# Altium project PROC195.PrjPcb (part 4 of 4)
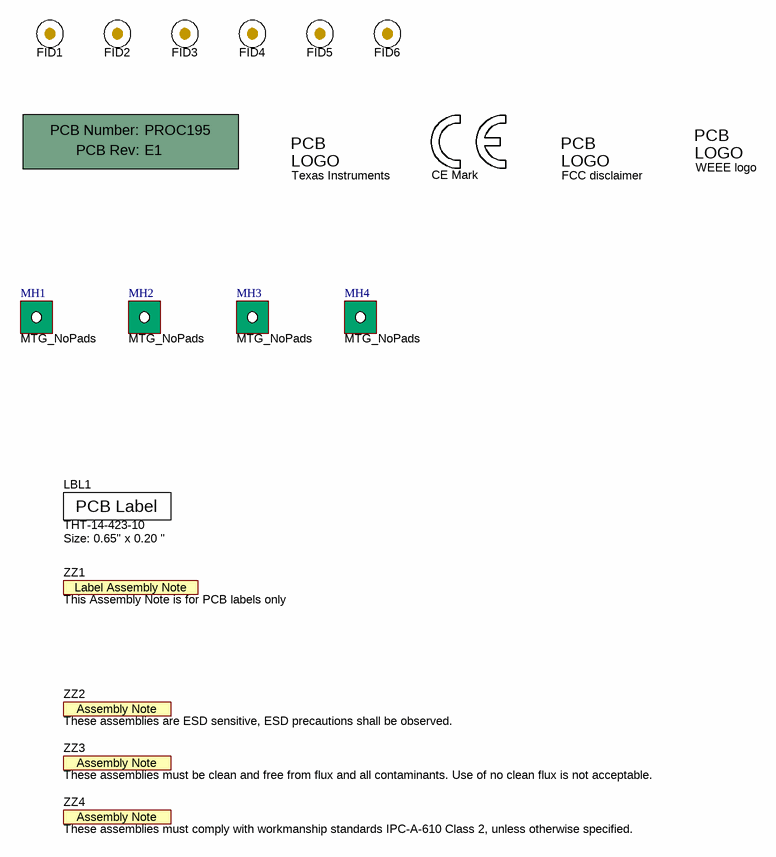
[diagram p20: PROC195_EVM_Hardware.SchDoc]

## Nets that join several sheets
1V8_LDO4: PROC195__FET_BOOST_REG (R265.1), PROC195_PMIC_BUCK (5 pins), PROC195_ADC (S1.1 S1.4)
3V3_LDO2: PROC195__FET_BOOST_REG (R57.1 R72.1), PROC195_PMIC_BUCK (C97.1 C98.1 TP7.1 U2.11), PROC195_CLK_LED_CURRENT_MON_TEMP_CONN (9 pins), PROC195_High_density_conn_1_2 (J1.28 R1.2)
5V0_LDO3: PROC195__FET_BOOST_REG (R160.1), PROC195_PMIC_BUCK (C99.1 C101.1 TP9.1 U2.15), PROC195_High_density_conn_1_2 (J1.34)
+1V2: PROC195_PMIC_BUCK (5 pins), PROC195_CLK_LED_CURRENT_MON_TEMP_CONN (R43.3)
GND: PROC195__FET_BOOST_REG (26 pins), PROC195_PMIC_BUCK (53 pins), PROC195_MCU_POWER_CAPS (147 pins), PROC195_SDFM, JTAG (9 pins), PROC195_OSPI_BOOTMODE (20 pins), PROC195_ADC (8 pins), PROC195_DAC (8 pins), PROC195_CLK_LED_CURRENT_MON_TEMP_CONN (23 pins), PROC195_RESET_CIRCUIT (21 pins), PROC195_High_density_conn_1_2 (20 pins), PROC195_High_density_conn3_4 (8 pins), PROC195_MIPI_Emulation_conn (10 pins)
VCC_1V2: PROC195_MCU_POWER_CAPS (47 pins), PROC195_CLK_LED_CURRENT_MON_TEMP_CONN (R43.4 TP16.1)
VDD_IO_3V3: PROC195_MCU_POWER_CAPS (20 pins), PROC195_CLK_LED_CURRENT_MON_TEMP_CONN (R44.4 TP17.1)
VDDA18_LDO_1V8: PROC195_MCU_POWER_CAPS (10 pins), PROC195_DAC (S2.1)
VDDA_3V3: PROC195_MCU_POWER_CAPS (8 pins), PROC195_ADC (C122.2 U11.4), PROC195_DAC (C152.1 U20.8)
VDDS18_LDO_1V8: PROC195_MCU_POWER_CAPS (11 pins), PROC195_CLK_LED_CURRENT_MON_TEMP_CONN (U7.5)
VMAIN_5V0: PROC195__FET_BOOST_REG (10 pins), PROC195_PMIC_BUCK (TP3.1), PROC195_MCU_POWER_CAPS (R12.2), PROC195_RESET_CIRCUIT (R249.1)
VMAIN_5V0_IN: PROC195__FET_BOOST_REG (5 pins), PROC195_High_density_conn_1_2 (J1.18 J1.20), PROC195_High_density_conn3_4 (J3.27)
VMAIN_12V0: PROC195__FET_BOOST_REG (C100.2 R190.2 U22.6), PROC195_PMIC_BUCK (18 pins)
VSYS_3V3_LDO1: PROC195__FET_BOOST_REG (R68.1 R279.2 R280.2), PROC195_PMIC_BUCK (10 pins), PROC195_EPWM (R104.2 R105.2), PROC195_SDFM, JTAG (12 pins), PROC195_OSPI_BOOTMODE (34 pins), PROC195_ADC (7 pins), PROC195_DAC (8 pins), PROC195_CLK_LED_CURRENT_MON_TEMP_CONN (13 pins), PROC195_RESET_CIRCUIT (19 pins), PROC195_MIPI_Emulation_conn (5 pins)
15W_PD: PROC195__FET_BOOST_REG (R42.2 R82.1 U14.3), PROC195_High_density_conn_1_2 (J1.26)
+1V2_PG: PROC195_PMIC_BUCK (R37.1 U3.1), PROC195_RESET_CIRCUIT (U21.1)
ADC0_AIN0/DAC_OUT_MUX_SEL: PROC195_SDFM, JTAG (U12.3), PROC195_DAC (U20.1 U20.5)
ADC_VREFHI_G2_G3: PROC195_EPWM (R239.1), PROC195_ADC (5 pins)
AM26x_ADC0_AIN0: PROC195_ADC (U1.V15), PROC195_DAC (U20.2)
AM26x_ADC0_AIN0/DAC_OUT: PROC195_DAC (U20.10), PROC195_High_density_conn_1_2 (J1.119)
AM26x_ADC0_AIN1: PROC195_ADC (U1.U15), PROC195_High_density_conn_1_2 (J1.117)
AM26x_ADC0_AIN2_P: PROC195_ADC (U1.T14), PROC195_High_density_conn_1_2 (J1.120)
AM26x_ADC0_AIN3_N: PROC195_ADC (U1.U14), PROC195_High_density_conn_1_2 (J1.118)
AM26x_ADC0_AIN4_P: PROC195_ADC (U1.U13), PROC195_High_density_conn_1_2 (J1.115)
AM26x_ADC0_AIN5_N: PROC195_ADC (U1.R14), PROC195_High_density_conn_1_2 (J1.113)
AM26x_ADC1_AIN0_P: PROC195_ADC (U1.T11), PROC195_High_density_conn_1_2 (J1.116)
AM26x_ADC1_AIN1_N: PROC195_ADC (U1.U11), PROC195_High_density_conn_1_2 (J1.114)
AM26x_ADC1_AIN2_P: PROC195_ADC (U1.T12), PROC195_High_density_conn_1_2 (J1.111)
AM26x_ADC1_AIN3_N: PROC195_ADC (U1.V12), PROC195_High_density_conn_1_2 (J1.109)
AM26x_ADC1_AIN4: PROC195_ADC (U1.U12), PROC195_High_density_conn_1_2 (J1.112)
AM26x_ADC1_AIN5: PROC195_ADC (U1.R12), PROC195_High_density_conn_1_2 (J1.110)
AM26x_ADC2_AIN0_P: PROC195_ADC (U1.R10), PROC195_High_density_conn_1_2 (J1.107)
AM26x_ADC2_AIN1_N: PROC195_ADC (U1.T10), PROC195_High_density_conn_1_2 (J1.105)
AM26x_ADC2_AIN2_P: PROC195_ADC (U1.U10), PROC195_High_density_conn_1_2 (J1.108)
AM26x_ADC2_AIN3_N: PROC195_ADC (U1.T9), PROC195_High_density_conn_1_2 (J1.106)
AM26x_ADC2_AIN4: PROC195_ADC (U1.V9), PROC195_High_density_conn_1_2 (J1.103)
AM26x_ADC2_AIN5: PROC195_ADC (U1.T8), PROC195_High_density_conn_1_2 (J1.101)
AM26x_ADC3_AIN0_P: PROC195_ADC (R240.1), PROC195_High_density_conn_1_2 (J1.104)
AM26x_ADC3_AIN1_N: PROC195_ADC (R241.1), PROC195_High_density_conn_1_2 (J1.102)
AM26x_ADC3_AIN2_P: PROC195_ADC (R242.1), PROC195_High_density_conn_1_2 (J1.99)
AM26x_ADC3_AIN3_N: PROC195_ADC (R243.1), PROC195_High_density_conn_1_2 (J1.97)
AM26x_ADC3_AIN4: PROC195_ADC (R244.1), PROC195_High_density_conn_1_2 (J1.100)
AM26x_ADC3_AIN5: PROC195_ADC (R272.1), PROC195_High_density_conn_1_2 (J1.98)
AM26x_ADC4_AIN0_P: PROC195_ADC (R273.1), PROC195_High_density_conn_1_2 (J1.95)
AM26x_ADC4_AIN1_N: PROC195_ADC (R274.1), PROC195_High_density_conn_1_2 (J1.93)
AM26x_ADC4_AIN2_P: PROC195_ADC (R275.1), PROC195_High_density_conn_1_2 (J1.96)
AM26x_ADC4_AIN3_N: PROC195_ADC (R276.1), PROC195_High_density_conn_1_2 (J1.94)
AM26x_ADC4_AIN4: PROC195_ADC (R277.1), PROC195_High_density_conn_1_2 (J1.91)
AM26x_ADC4_AIN5: PROC195_ADC (R278.1), PROC195_High_density_conn_1_2 (J1.89)
AM26x_ADC_CAL0: PROC195_ADC (U1.U16), PROC195_High_density_conn_1_2 (J1.92)
AM26x_ADC_CAL1: PROC195_ADC (R77.2), PROC195_High_density_conn_1_2 (J1.90)
AM26x_ADC_CAL2: PROC195_DAC (R283.2), PROC195_High_density_conn_1_2 (J2.112)
AM26x_ADC_CAL3: PROC195_DAC (R297.2), PROC195_High_density_conn_1_2 (J2.110)
AM26x_ADC_R0_AIN0_P: PROC195_DAC (R289.2), PROC195_High_density_conn_1_2 (J2.120)
AM26x_ADC_R0_AIN1_N: PROC195_EPWM (R261.1), PROC195_High_density_conn_1_2 (J2.118)
AM26x_ADC_R0_AIN2_P: PROC195_DAC (R287.2), PROC195_High_density_conn_1_2 (J2.119)
AM26x_ADC_R0_AIN3_N: PROC195_DAC (R285.2), PROC195_High_density_conn_1_2 (J2.117)
AM26x_ADC_R1_AIN0_P: PROC195_EPWM (R263.1), PROC195_High_density_conn_1_2 (J2.116)
AM26x_ADC_R1_AIN1_N: PROC195_DAC (R291.2), PROC195_High_density_conn_1_2 (J2.114)
AM26x_ADC_R1_AIN2_P: PROC195_DAC (R295.2), PROC195_High_density_conn_1_2 (J2.115)
AM26x_ADC_R1_AIN3_N: PROC195_DAC (R293.2), PROC195_High_density_conn_1_2 (J2.113)
AM26x_EPWM0_A: PROC195_EPWM (R106.1), PROC195_High_density_conn_1_2 (J1.15)
AM26x_EPWM0_B: PROC195_EPWM (R107.1), PROC195_High_density_conn_1_2 (J1.13)
AM26x_EPWM1_A: PROC195_EPWM (R109.1), PROC195_High_density_conn_1_2 (J1.11)
AM26x_EPWM1_B: PROC195_EPWM (R111.1), PROC195_High_density_conn_1_2 (J1.9)
AM26x_EPWM2_A: PROC195_EPWM (R112.1), PROC195_High_density_conn_1_2 (J1.7)
AM26x_EPWM2_B: PROC195_EPWM (R113.1), PROC195_High_density_conn_1_2 (J1.5)
AM26x_EPWM3_A: PROC195_EPWM (R114.1), PROC195_High_density_conn_1_2 (J1.3)
AM26x_EPWM3_B: PROC195_EPWM (R115.1), PROC195_High_density_conn_1_2 (J1.1)
AM26x_EPWM4_A: PROC195_EPWM (R116.1), PROC195_High_density_conn_1_2 (J1.16)
AM26x_EPWM4_B: PROC195_EPWM (R117.1), PROC195_High_density_conn_1_2 (J1.14)
AM26x_EPWM5_A: PROC195_EPWM (R118.1), PROC195_High_density_conn_1_2 (J1.12)
AM26x_EPWM5_B: PROC195_EPWM (R120.1), PROC195_High_density_conn_1_2 (J1.10)
AM26x_EPWM6_A: PROC195_EPWM (R123.1), PROC195_High_density_conn_1_2 (J1.8)
AM26x_EPWM6_B: PROC195_EPWM (R125.1), PROC195_High_density_conn_1_2 (J1.6)
AM26x_EPWM7_A: PROC195_EPWM (R127.1), PROC195_High_density_conn_1_2 (J1.4)
AM26x_EPWM7_B: PROC195_EPWM (R128.1), PROC195_High_density_conn_1_2 (J1.2)
AM26x_EPWM8_A: PROC195_EPWM (R130.1), PROC195_High_density_conn_1_2 (J2.60)
AM26x_EPWM8_B: PROC195_EPWM (R131.1), PROC195_High_density_conn_1_2 (J2.58)
AM26x_EPWM9_A: PROC195_EPWM (R133.1), PROC195_High_density_conn_1_2 (J2.56)
AM26x_EPWM9_B: PROC195_EPWM (R134.1), PROC195_High_density_conn_1_2 (J2.54)
AM26x_EQEP0_A: PROC195_EPWM (R83.1), PROC195_High_density_conn_1_2 (J1.71)
AM26x_EQEP0_B: PROC195_EPWM (R85.1), PROC195_High_density_conn_1_2 (J1.69)
AM26x_EQEP0_INDEX: PROC195_EPWM (U1.D11), PROC195_High_density_conn_1_2 (J1.65)
AM26x_EQEP0_STROBE: PROC195_EPWM (U1.C12), PROC195_High_density_conn_1_2 (J1.67)
AM26x_FSIRX0_CLK: PROC195_RESET_CIRCUIT (U24.3), PROC195_High_density_conn_1_2 (J1.55)
AM26x_FSIRX0_DATA0: PROC195_RESET_CIRCUIT (U24.6), PROC195_High_density_conn_1_2 (J1.59)
AM26x_FSIRX0_DATA1: PROC195_RESET_CIRCUIT (U24.10), PROC195_High_density_conn_1_2 (J1.57)
AM26x_FSITX0_CLK: PROC195_DAC (U13.3), PROC195_High_density_conn_1_2 (J1.49)
AM26x_FSITX0_DATA0: PROC195_DAC (U13.6), PROC195_High_density_conn_1_2 (J1.53)
AM26x_FSITX0_DATA1: PROC195_DAC (U13.10), PROC195_High_density_conn_1_2 (J1.51)
AM26x_GPIO15: PROC195_RESET_CIRCUIT (U24.13), PROC195_High_density_conn3_4 (J3.57)
AM26x_I2C1_SCL: PROC195_SDFM, JTAG (R268.1 U25.2), PROC195_High_density_conn3_4 (J3.70)
AM26x_I2C1_SDA: PROC195_SDFM, JTAG (R266.1 U1.A3), PROC195_High_density_conn3_4 (J3.72)
AM26x_I2C2_SCL: PROC195_SDFM, JTAG (R158.1 U1.C6), PROC195_High_density_conn_1_2 (J1.61)
AM26x_I2C2_SDA: PROC195_SDFM, JTAG (R157.1 U1.A5), PROC195_High_density_conn_1_2 (J1.63)
AM26x_LIN1_RXD: PROC195_OSPI_BOOTMODE (U1.A9), PROC195_High_density_conn_1_2 (J1.37)
AM26x_LIN1_TXD: PROC195_OSPI_BOOTMODE (R211.1), PROC195_High_density_conn_1_2 (J1.35)
AM26x_MCAN0_RX: PROC195_SDFM, JTAG (U1.B6), PROC195_High_density_conn_1_2 (J1.38)
AM26x_MCAN0_TX: PROC195_SDFM, JTAG (R129.1), PROC195_High_density_conn_1_2 (J1.36)
AM26x_MCAN1_RX: PROC195_SDFM, JTAG (U25.3), PROC195_High_density_conn3_4 (J3.56)
AM26x_MCAN1_TX: PROC195_SDFM, JTAG (R132.1), PROC195_High_density_conn3_4 (J3.54)
AM26x_SDFM0_CLK0: PROC195_SDFM, JTAG (R76.1), PROC195_High_density_conn_1_2 (J1.54)
AM26x_SDFM0_D0: PROC195_SDFM, JTAG (U1.D14), PROC195_High_density_conn_1_2 (J1.60)
AM26x_SDFM0_D1: PROC195_SDFM, JTAG (U1.D13), PROC195_High_density_conn_1_2 (J1.58)
AM26x_SDFM0_D2: PROC195_SDFM, JTAG (U1.C13), PROC195_High_density_conn_1_2 (J1.56)
AM26x_SDFM0_D3: PROC195_SDFM, JTAG (U1.C14), PROC195_High_density_conn_1_2 (J1.50)
AM26x_SPI0_CLK: PROC195_DAC (U13.2), PROC195_High_density_conn_1_2 (J2.34)
AM26x_SPI0_CS0: PROC195_DAC (U13.14), PROC195_High_density_conn_1_2 (J2.36)
AM26x_SPI0_D0: PROC195_DAC (U13.5), PROC195_High_density_conn_1_2 (J2.32)
AM26x_SPI0_D1: PROC195_DAC (U13.11), PROC195_High_density_conn_1_2 (J2.30)
AM26x_SPI3_CLK: PROC195_ADC (U18.2), PROC195_High_density_conn_1_2 (J1.41)
AM26x_SPI3_CS0: PROC195_ADC (U18.14), PROC195_High_density_conn_1_2 (J1.39)
AM26x_SPI3_D0: PROC195_ADC (U18.5), PROC195_High_density_conn_1_2 (J1.45)
AM26x_SPI3_D1: PROC195_ADC (U18.11), PROC195_High_density_conn_1_2 (J1.43)
AM26x_TCK: PROC195_SDFM, JTAG (U1.B3), PROC195_MIPI_Emulation_conn (R61.1 R314.2)
AM26x_TDI: PROC195_SDFM, JTAG (U1.C5), PROC195_MIPI_Emulation_conn (R63.1 R316.2)
AM26x_TDO: PROC195_SDFM, JTAG (R162.1), PROC195_MIPI_Emulation_conn (R62.1 R315.2)
AM26x_TMS: PROC195_SDFM, JTAG (U1.D5), PROC195_MIPI_Emulation_conn (R60.1 R313.2)
AM26x_UART0_RXD: PROC195_OSPI_BOOTMODE (U1.A7), PROC195_High_density_conn_1_2 (J1.33), PROC195_MIPI_Emulation_conn (J7.9)
AM26x_UART0_TXD: PROC195_OSPI_BOOTMODE (R208.1), PROC195_High_density_conn_1_2 (J1.31), PROC195_MIPI_Emulation_conn (J7.10)
AM26x_UART2_RXD: PROC195_OSPI_BOOTMODE (R212.1), PROC195_High_density_conn_1_2 (J2.26)
AM26x_UART2_TXD: PROC195_OSPI_BOOTMODE (U1.A8), PROC195_High_density_conn_1_2 (J2.28)
AM26x_USB0_DM: PROC195_SDFM, JTAG (R165.1), PROC195_High_density_conn_1_2 (J2.40)
AM26x_USB0_DP: PROC195_SDFM, JTAG (R168.1), PROC195_High_density_conn_1_2 (J2.38)
AM26x_VREFHI1: PROC195_ADC (S1.3), PROC195_High_density_conn_1_2 (J1.85)
AM26x_VREFHI2: PROC195_ADC (S1.6), PROC195_High_density_conn_1_2 (J1.83)
AM26x_VREFLO: PROC195_ADC (10 pins), PROC195_High_density_conn_1_2 (J1.87)
DAC_SPI3_CLK: PROC195_ADC (U18.3), PROC195_MIPI_Emulation_conn (J7.13)
DAC_SPI3_CS0: PROC195_ADC (U18.13), PROC195_MIPI_Emulation_conn (J7.16)
DAC_SPI3_D0: PROC195_ADC (U18.6), PROC195_MIPI_Emulation_conn (J7.14)
DAC_SPI3_D1: PROC195_ADC (U18.10), PROC195_MIPI_Emulation_conn (J7.15)
DAC_TCK: PROC195_High_density_conn_1_2 (J1.22), PROC195_MIPI_Emulation_conn (J7.4 R314.1)
DAC_TDI: PROC195_High_density_conn_1_2 (J1.19), PROC195_MIPI_Emulation_conn (J7.5 R316.1)
DAC_TDO: PROC195_High_density_conn_1_2 (J1.21), PROC195_MIPI_Emulation_conn (J7.6 R315.1)
DAC_TMS: PROC195_High_density_conn_1_2 (J1.24), PROC195_MIPI_Emulation_conn (J7.3 R313.1)
EXT_VMON2: PROC195_PMIC_BUCK (U2.10), PROC195_High_density_conn3_4 (J3.59)
EXT_VREF2: PROC195_ADC (S1.5 U11.5), PROC195_DAC (U11.14)
IOEXP_OUT_P6: PROC195_SDFM, JTAG (U12.9), PROC195_High_density_conn_1_2 (J2.5)
IOEXP_OUT_P7: PROC195_SDFM, JTAG (U12.10), PROC195_High_density_conn_1_2 (J2.9)
JTAG_RESETn: PROC195_RESET_CIRCUIT (U4.3), PROC195_MIPI_Emulation_conn (R40.1 R64.1)
MCU_GPIO1: PROC195_OSPI_BOOTMODE (R140.1), PROC195_High_density_conn_1_2 (J1.52)
MCU_GPIO41: PROC195_DAC (R233.1 R236.1), PROC195_High_density_conn_1_2 (J2.19)
MCU_GPIO42: PROC195_DAC (R234.1 R235.1), PROC195_High_density_conn_1_2 (J2.17)
MCU_GPIO63: PROC195_EPWM (R135.1), PROC195_High_density_conn_1_2 (J2.52)
MCU_GPIO64: PROC195_EPWM (R136.1), PROC195_High_density_conn_1_2 (J2.50)
MCU_GPIO67: PROC195_EPWM (R143.1), PROC195_High_density_conn_1_2 (J2.59)
MCU_GPIO68: PROC195_EPWM (R144.1), PROC195_High_density_conn_1_2 (J2.57)
MCU_GPIO69: PROC195_EPWM (R146.1), PROC195_High_density_conn_1_2 (J2.55)
MCU_GPIO70: PROC195_EPWM (R147.1), PROC195_High_density_conn_1_2 (J2.53)
MCU_GPIO73: PROC195_EPWM (R282.1), PROC195_High_density_conn_1_2 (J1.75)
MCU_GPIO74: PROC195_EPWM (R262.1), PROC195_High_density_conn_1_2 (J2.25)
MCU_GPIO82: PROC195_SDFM, JTAG (U1.A2 U25.1), PROC195_High_density_conn_1_2 (J1.48)
MCU_GPIO85: PROC195_EPWM (R104.1 R110.1), PROC195_High_density_conn3_4 (J3.99)
MCU_GPIO86: PROC195_EPWM (R105.1 R108.1), PROC195_High_density_conn3_4 (J3.97)
MCU_GPIO119: PROC195_EPWM (R173.1), PROC195_High_density_conn3_4 (J3.66)
MCU_GPIO120: PROC195_EPWM (R172.1), PROC195_High_density_conn3_4 (J3.68)
MCU_GPIO121: PROC195_RESET_CIRCUIT (R312.2), PROC195_High_density_conn_1_2 (J1.70)
MCU_GPIO124: PROC195_SDFM, JTAG (R214.1), PROC195_High_density_conn_1_2 (J1.72)
MCU_GPIO126: PROC195_SDFM, JTAG (U1.B15), PROC195_High_density_conn_1_2 (J1.73)
MCU_GPIO136: PROC195_OSPI_BOOTMODE (R217.1), PROC195_High_density_conn_1_2 (J2.23)
MCU_GPIO137: PROC195_OSPI_BOOTMODE (U1.A12), PROC195_High_density_conn_1_2 (J2.21)
MCU_GPIO138: PROC195_RESET_CIRCUIT (R138.2), PROC195_High_density_conn_1_2 (J1.74)
MCU_I2C0_SCL: PROC195_SDFM, JTAG (U12.12), PROC195_OSPI_BOOTMODE (R38.1 R202.1), PROC195_CLK_LED_CURRENT_MON_TEMP_CONN (5 pins), PROC195_High_density_conn_1_2 (J1.23), PROC195_MIPI_Emulation_conn (J7.12)
MCU_I2C0_SDA: PROC195_SDFM, JTAG (U12.13), PROC195_OSPI_BOOTMODE (R39.1 R203.1), PROC195_CLK_LED_CURRENT_MON_TEMP_CONN (5 pins), PROC195_High_density_conn_1_2 (J1.25), PROC195_MIPI_Emulation_conn (J7.11)
MCU_INTn: PROC195_SDFM, JTAG (U1.A15), PROC195_RESET_CIRCUIT (R41.2 U23.5)
MCU_PORz: PROC195_SDFM, JTAG (U12.1), PROC195_OSPI_BOOTMODE (R231.1 U16.2), PROC195_RESET_CIRCUIT (TP18.1 U1.R2 U4.4), PROC195_High_density_conn_1_2 (J1.29)
MCU_RESETn: PROC195_OSPI_BOOTMODE (R232.1), PROC195_RESET_CIRCUIT (R253.2 U1.C3 U23.2)
MCU_SPI0_CLK: PROC195_OSPI_BOOTMODE (R225.1 U1.A11), PROC195_DAC (R298.2 U13.4)
MCU_SPI0_CS0: PROC195_OSPI_BOOTMODE (U1.C11), PROC195_DAC (R301.2 U13.12)
MCU_SPI0_D0: PROC195_OSPI_BOOTMODE (R226.1 U1.C10), PROC195_DAC (R299.2 U13.7)
MCU_SPI0_D1: PROC195_OSPI_BOOTMODE (U1.B11), PROC195_DAC (R300.2 U13.9)
MCU_SPI1_CLK: PROC195_OSPI_BOOTMODE (U1.A10), PROC195_RESET_CIRCUIT (R254.2 U24.4)
MCU_SPI1_CS0: PROC195_OSPI_BOOTMODE (U1.C9), PROC195_RESET_CIRCUIT (R257.2 U24.12)
MCU_SPI1_D0: PROC195_OSPI_BOOTMODE (U1.B10), PROC195_RESET_CIRCUIT (R255.2 U24.7)
MCU_SPI1_D1: PROC195_OSPI_BOOTMODE (U1.D9), PROC195_RESET_CIRCUIT (R256.2 U24.9)
MCU_SPI3_CLK: PROC195_OSPI_BOOTMODE (R204.1), PROC195_ADC (R304.2 U18.4)
MCU_SPI3_CS0: PROC195_OSPI_BOOTMODE (U1.D7), PROC195_ADC (R308.2 U18.12)
MCU_SPI3_D0: PROC195_OSPI_BOOTMODE (R207.1), PROC195_ADC (R306.2 U18.7)
MCU_SPI3_D1: PROC195_OSPI_BOOTMODE (U1.B7), PROC195_ADC (R307.2 U18.9)
MII_RST#: PROC195_SDFM, JTAG (U12.4), PROC195_High_density_conn3_4 (J3.101)
MII_RX_ER: PROC195_EPWM (R4.1), PROC195_High_density_conn_1_2 (J2.15)
OSPI0_ECS: PROC195_EPWM (U1.H1), PROC195_OSPI_BOOTMODE (R185.1 U15.A5)
OSPI0_RESET_OUTn: PROC195_EPWM (U1.J1), PROC195_OSPI_BOOTMODE (R205.1 U16.1)
PHY0_25MHZ_CLK: PROC195_CLK_LED_CURRENT_MON_TEMP_CONN (R210.2), PROC195_High_density_conn3_4 (J3.117)
PHY1_25MHZ_CLK: PROC195_CLK_LED_CURRENT_MON_TEMP_CONN (R213.2), PROC195_High_density_conn3_4 (J3.119)
PMIC_COMP1_IN+: PROC195_PMIC_BUCK (U2.21), PROC195_High_density_conn3_4 (J3.37)
PMIC_COMP1_IN-: PROC195_PMIC_BUCK (U2.24), PROC195_High_density_conn3_4 (J3.35)
PMIC_COMP2_IN+: PROC195_PMIC_BUCK (U2.28), PROC195_High_density_conn3_4 (J3.33)
PMIC_COMP2_IN-: PROC195_PMIC_BUCK (U2.25), PROC195_High_density_conn3_4 (J3.31)
PMIC_DIAG_OUT: PROC195_PMIC_BUCK (U2.32), PROC195_RESET_CIRCUIT (R84.2)
PMIC_INTn: PROC195_PMIC_BUCK (U2.22), PROC195_RESET_CIRCUIT (R311.2)
PMIC_nRST: PROC195_PMIC_BUCK (U2.13), PROC195_RESET_CIRCUIT (R247.1)
PMIC_SAFE_OUT1: PROC195_PMIC_BUCK (R25.2), PROC195_High_density_conn_1_2 (R1.1 R2.2 R74.2)
PMIC_SAFE_OUT2: PROC195__FET_BOOST_REG (Q4.1 R281.2), PROC195_PMIC_BUCK (U2.27), PROC195_High_density_conn3_4 (J3.29)
PMIC_SPI1/FSIRX0_MUX_SEL: PROC195_SDFM, JTAG (U12.2), PROC195_RESET_CIRCUIT (R258.1 U24.1)
PMIC_SPI1_CLK: PROC195_PMIC_BUCK (R19.2 TP11.1 U2.33), PROC195_RESET_CIRCUIT (U24.2)
PMIC_SPI1_CS0: PROC195_PMIC_BUCK (R22.2 TP14.1 U2.36), PROC195_RESET_CIRCUIT (U24.14)
PMIC_SPI1_D0: PROC195_PMIC_BUCK (R20.2 TP12.1 U2.35), PROC195_RESET_CIRCUIT (U24.5)
PMIC_SPI1_D1: PROC195_PMIC_BUCK (R21.2 R24.1), PROC195_RESET_CIRCUIT (U24.11)
PMIC_WAKE2: PROC195_PMIC_BUCK (U2.43), PROC195_High_density_conn_1_2 (J1.30)
PR0_PRU0_GPIO0: PROC195_EPWM (U1.K17), PROC195_High_density_conn3_4 (J3.102)
PR0_PRU0_GPIO1: PROC195_EPWM (U1.K18), PROC195_High_density_conn3_4 (J3.104)
PR0_PRU0_GPIO2: PROC195_EPWM (U1.J18), PROC195_High_density_conn3_4 (J3.106)
PR0_PRU0_GPIO3: PROC195_EPWM (U1.J17), PROC195_High_density_conn3_4 (J3.108)
PR0_PRU0_GPIO4: PROC195_EPWM (U1.K16), PROC195_High_density_conn3_4 (J3.113)
PR0_PRU0_GPIO5: PROC195_EPWM (U1.G17), PROC195_High_density_conn3_4 (J3.111)
PR0_PRU0_GPIO6: PROC195_EPWM (U1.K15), PROC195_High_density_conn3_4 (J3.100)
PR0_PRU0_GPIO8: PROC195_EPWM (U1.G15), PROC195_High_density_conn3_4 (J3.87)
PR0_PRU0_GPIO9: PROC195_EPWM (U1.F17), PROC195_High_density_conn3_4 (J3.105)
PR0_PRU0_GPIO10: PROC195_EPWM (U1.G18), PROC195_High_density_conn3_4 (J3.109)
PR0_PRU0_GPIO11: PROC195_EPWM (R119.1), PROC195_High_density_conn3_4 (J3.114)
PR0_PRU0_GPIO12: PROC195_EPWM (R121.1), PROC195_High_density_conn3_4 (J3.116)
PR0_PRU0_GPIO13: PROC195_EPWM (R122.1), PROC195_High_density_conn3_4 (J3.118)
PR0_PRU0_GPIO14: PROC195_EPWM (R124.1), PROC195_High_density_conn3_4 (J3.120)
PR0_PRU0_GPIO15: PROC195_EPWM (U1.L16), PROC195_High_density_conn3_4 (J3.115)
PR0_PRU0_GPIO16: PROC195_EPWM (R126.1), PROC195_High_density_conn3_4 (J3.112)
PR0_PRU1_GPIO0: PROC195_EPWM (R149.1), PROC195_High_density_conn3_4 (J3.78)
PR0_PRU1_GPIO1: PROC195_EPWM (R150.1), PROC195_High_density_conn3_4 (J3.80)
PR0_PRU1_GPIO2: PROC195_EPWM (R151.1), PROC195_High_density_conn3_4 (J3.82)
PR0_PRU1_GPIO3: PROC195_EPWM (R152.1), PROC195_High_density_conn3_4 (J3.84)
PR0_PRU1_GPIO4: PROC195_EPWM (R153.1), PROC195_High_density_conn3_4 (J3.93)
PR0_PRU1_GPIO5: PROC195_EPWM (R154.1), PROC195_High_density_conn3_4 (J3.95)
PR0_PRU1_GPIO6: PROC195_EPWM (R155.1), PROC195_High_density_conn3_4 (J3.76)
PR0_PRU1_GPIO8: PROC195_EPWM (R156.1), PROC195_High_density_conn3_4 (J3.89)
PR0_PRU1_GPIO9: PROC195_EPWM (R159.1), PROC195_High_density_conn3_4 (J3.85)
PR0_PRU1_GPIO10: PROC195_EPWM (R161.1), PROC195_High_density_conn3_4 (J3.83)
PR0_PRU1_GPIO11: PROC195_EPWM (R163.1), PROC195_High_density_conn3_4 (J3.90)
PR0_PRU1_GPIO12: PROC195_EPWM (R164.1), PROC195_High_density_conn3_4 (J3.92)
PR0_PRU1_GPIO13: PROC195_EPWM (R167.1), PROC195_High_density_conn3_4 (J3.94 R8.1)
PR0_PRU1_GPIO14: PROC195_EPWM (R169.1), PROC195_High_density_conn3_4 (J3.96 R5.1)
PR0_PRU1_GPIO15: PROC195_EPWM (R170.1), PROC195_High_density_conn3_4 (J3.91)
PR0_PRU1_GPIO16: PROC195_EPWM (R171.1), PROC195_High_density_conn3_4 (J3.88)
R_MCU_GPIO119: PROC195_EPWM (R173.2 U1.D15), PROC195_MIPI_Emulation_conn (R93.1)
R_MCU_GPIO120: PROC195_EPWM (R172.2 U1.C15), PROC195_MIPI_Emulation_conn (R96.1)
R_PR0_PRU1_GPIO0: PROC195_EPWM (R149.2 U1.F18), PROC195_MIPI_Emulation_conn (R86.2)
R_PR0_PRU1_GPIO1: PROC195_EPWM (R150.2 U1.G16), PROC195_MIPI_Emulation_conn (R87.2)
R_PR0_PRU1_GPIO2: PROC195_EPWM (R151.2 U1.E17), PROC195_MIPI_Emulation_conn (R88.2)
R_PR0_PRU1_GPIO3: PROC195_EPWM (R152.2 U1.E18), PROC195_MIPI_Emulation_conn (R89.2)
R_PR0_PRU1_GPIO4: PROC195_EPWM (R153.2 U1.F16), PROC195_MIPI_Emulation_conn (R103.1)
R_PR0_PRU1_GPIO5: PROC195_EPWM (R154.2 U1.F15), PROC195_MIPI_Emulation_conn (R98.1)
R_PR0_PRU1_GPIO6: PROC195_EPWM (R155.2 U1.E16), PROC195_MIPI_Emulation_conn (R102.1)
R_PR0_PRU1_GPIO8: PROC195_EPWM (R156.2 U1.D18), PROC195_MIPI_Emulation_conn (R101.1)
R_PR0_PRU1_GPIO9: PROC195_EPWM (R159.2 U1.C18), PROC195_MIPI_Emulation_conn (R99.1)
R_PR0_PRU1_GPIO10: PROC195_EPWM (R161.2 U1.D17), PROC195_MIPI_Emulation_conn (R100.1)
R_PR0_PRU1_GPIO11: PROC195_EPWM (R137.1 R163.2), PROC195_MIPI_Emulation_conn (R92.2)
R_PR0_PRU1_GPIO12: PROC195_EPWM (R139.1 R164.2), PROC195_MIPI_Emulation_conn (R94.2)
R_PR0_PRU1_GPIO13: PROC195_EPWM (R141.1 R167.2), PROC195_MIPI_Emulation_conn (R95.2)
R_PR0_PRU1_GPIO14: PROC195_EPWM (R142.1 R169.2), PROC195_MIPI_Emulation_conn (R97.2)
R_PR0_PRU1_GPIO15: PROC195_EPWM (R170.2 U1.A17), PROC195_MIPI_Emulation_conn (R91.2)
R_PR0_PRU1_GPIO16: PROC195_EPWM (R145.1 R171.2), PROC195_MIPI_Emulation_conn (R90.2)
RES0_PWMOUT0: PROC195_High_density_conn_1_2 (J2.48), PROC195_High_density_conn3_4 (R8.2)
RES0_PWMOUT1: PROC195_High_density_conn_1_2 (J2.46), PROC195_High_density_conn3_4 (R5.2)
RGMII1_ETH1_CLK: PROC195_CLK_LED_CURRENT_MON_TEMP_CONN (R3.2), PROC195_High_density_conn_1_2 (J2.1)
RGMII1_INTn: PROC195_EPWM (R79.1), PROC195_High_density_conn_1_2 (J2.7)
RGMII1_RD0: PROC195_DAC (R264.2), PROC195_High_density_conn_1_2 (J2.20)
RGMII1_RD1: PROC195_DAC (R284.2), PROC195_High_density_conn_1_2 (J2.18)
RGMII1_RD2: PROC195_DAC (R286.2), PROC195_High_density_conn_1_2 (J2.16)
RGMII1_RD3: PROC195_DAC (R288.2), PROC195_High_density_conn_1_2 (J2.14)
RGMII1_RST: PROC195_SDFM, JTAG (U12.5), PROC195_High_density_conn_1_2 (J2.11)
RGMII1_RX_CTL: PROC195_DAC (R290.2), PROC195_High_density_conn_1_2 (J2.13)
RGMII1_RXC: PROC195_DAC (U1.R17), PROC195_High_density_conn_1_2 (J2.22)
RGMII1_TD0: PROC195_DAC (R6.2), PROC195_High_density_conn_1_2 (J2.8)
RGMII1_TD1: PROC195_DAC (R292.2), PROC195_High_density_conn_1_2 (J2.6)
RGMII1_TD2: PROC195_DAC (R294.2), PROC195_High_density_conn_1_2 (J2.4)
RGMII1_TD3: PROC195_DAC (R296.2), PROC195_High_density_conn_1_2 (J2.2)
RGMII1_TX_CTL: PROC195_DAC (R7.2), PROC195_High_density_conn_1_2 (J2.3)
RGMII1_TXC: PROC195_DAC (R238.2), PROC195_High_density_conn_1_2 (J2.10)
SAFETY_ERRORn: PROC195__FET_BOOST_REG (Q3.1), PROC195_PMIC_BUCK (U2.18), PROC195_RESET_CIRCUIT (U1.D4)
SoC_CLKIN: PROC195_CLK_LED_CURRENT_MON_TEMP_CONN (U7.4), PROC195_RESET_CIRCUIT (U1.T1)
SPI0/FSITX0_MUX_SEL: PROC195_SDFM, JTAG (U12.7), PROC195_DAC (R302.1 U13.1)
SPI3_MUX_SEL: PROC195_SDFM, JTAG (U12.8), PROC195_ADC (R305.2 U18.1)
USER_LED0: PROC195_SDFM, JTAG (R215.1), PROC195_CLK_LED_CURRENT_MON_TEMP_CONN (D2.1)
USER_LED1: PROC195_OSPI_BOOTMODE (R237.1), PROC195_CLK_LED_CURRENT_MON_TEMP_CONN (D3.1)

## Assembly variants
PROC195E1(001)_AM261: not fitted C70 C169 R1 R2 R3 R4 R5 R8 R9 R11 R14 R19 R20 R21 R22 R23 R28 R31 R49 R50 R51 R53 R73 R75 R77 R82 R86 R87 R88 R89 R90 R91 R92 R93 R94 R95 R96 R97 R98 R99 R100 R101 R102 R103 R138 R140 R183 R188 R199 R214 R232 R239 R261 R263 R283 R285 R287 R289 R291 R293 R295 R297 R298 R299 R310 R312; alternate parts U3 -> CMP-0093447-1
PROC195E1(002)_AM263P: not fitted C70 C169 R1 R2 R3 R4 R14 R19 R20 R21 R22 R23 R28 R31 R49 R50 R51 R53 R79 R82 R86 R87 R88 R89 R90 R91 R92 R93 R94 R95 R96 R97 R98 R99 R100 R101 R102 R103 R138 R140 R165 R168 R183 R188 R199 R214 R232 R262 R264 R282 R284 R286 R288 R290 R292 R294 R296 R298 R299 R312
